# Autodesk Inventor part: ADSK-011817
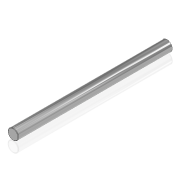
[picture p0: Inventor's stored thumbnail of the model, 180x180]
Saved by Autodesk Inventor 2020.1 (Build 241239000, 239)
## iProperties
Created: 1999-12
Part Number: ADSK-011817
Document SubType Name: Modeling
Designer: glanglot
Material: Générique
Density: 1 g/cm^3
Appearance: Chrom - poliert
Mass: 91.0869 g
Surface Area: 188.195 cm^2
Volume: 91.0869 cm^3
Control State: 0
Master: False
Checked Out: False
Shininess: 0.0
Length Units: 11269
Angle Units: 11279
Time Units: 11290
Mass Units: 11283
Length Display Precision: 3
Angle Display Precision: 2
Compacted: True
Dimensions: 20x20x290 mm
Mass: 0,091 kg
DocNumber: ADSK-011817.ipt
Folder: 01 - Themengebiete\Simplification\01 - Packaging machine\
VDS_Category: 3D Komponenten
Density: 0.0
Volumn: 0.0
Area: 0.0
PropertySet Name: Model Information
Author: glanglot
Revision Number: -
Title: shaft
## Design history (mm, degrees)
node "Solide1"
  node "Extrusion1" dims "d1" = 290, "d2" = 0
  node "Chamfer1" dims "d3" = 0.79375, "d4" = 0.79375, "d5" = 45 deg
sketch "Sketch1"
  geometry: C1 r 10 at (-34.64, 42.56)
  constraints: 1 centre point, 1 other
  dimensions: "d0" = 20 diameter of C1
node "Corps solides"
node "Corps surfaciques"
